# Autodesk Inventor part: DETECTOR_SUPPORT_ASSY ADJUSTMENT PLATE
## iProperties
Shininess: 64.0
Length Units: 11272
Angle Units: 11279
Time Units: 11290
Mass Units: 11286
Length Display Precision: 3
Angle Display Precision: 2
Compacted: True
Part Number: DETECTOR_SUPPORT_ASSY ADJUSTMENT PLATE
Document SubType Name: Modeling
Created: 2004-08
Designer: John Blackburn
Material: ALUMINUM
Manufacturer: Standard
Standards Organization: Custom
Density: 0.0
Volumn: 0.0
Area: 0.0
PropertySet Name: Model Information
Control State: 0
Master: False
Checked Out: False
Author: John Blackburn
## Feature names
1. ExtrusionBlind1
2. ExtrusionThru1
3. ExtrusionThru2
4. ExtrusionThru3
5. ExtrusionThru4
6. AM_HOLE_SI0030_1 [Hole]
7. Hole1
8. Hole2
9. Hole3
